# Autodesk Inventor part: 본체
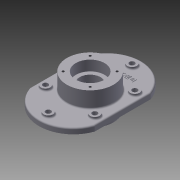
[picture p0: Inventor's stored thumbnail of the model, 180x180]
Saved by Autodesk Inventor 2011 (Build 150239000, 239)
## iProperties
Created: 2015-02
Part Number: 본체
Material: 알루미늄-6061
Document SubType Name: Modeling
Designer: Administrator
Mass: 1637.29 g
Surface Area: 924.766 cm^2
Volume: 604.167 cm^3
Density: 2.71 g/cm^3
Author: Administrator
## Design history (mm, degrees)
sketch "스케치1"
  geometry: C1 r 50 at (0, 0); 1 further point
  constraints: 1 centre point, 1 coincident
  dimensions: "d0" = 100 diameter of C1
extrude "돌출1" new body sketch "스케치1" distance "d1" = 23; taper "d2" = 0 deg
sketch "스케치2"
  geometry: L1 (-70, 0)-(-70, -60); L2 (70, -60)-(70, 60); L3 (-70, 60)-(-70, 0); A1 r 74 centre (0, -36) between (-70, -60) and (70, -60); A2 r 74 centre (0, 36) between (70, 60) and (-70, 60)
  constraints: 6 end point, 4 point on circle, 2 centre point
extrude "돌출2" join sketch "스케치2" distance "d3" = 12; taper "d4" = 0 deg
sketch "스케치3"
  geometry: C1 r 50 at (0, 0); 1 further point
  constraints: 1 centre point, 1 coincident
extrude "돌출3" join sketch "스케치3" distance "d5" = 35; taper "d6" = 0 deg
sketch "스케치6"
  geometry: C1 r 50 at (0, 0) reference; C2 r 31 at (0, 0)
  constraints: 1 centre point, 1 coincident
extrude "돌출5" cut sketch "스케치6" distance "d18" = 22; taper "d19" = 0 deg
sketch "스케치7"
  geometry: C1 r 50 at (0, 0) reference; C2 r 31 at (0, 0)
  constraints: 1 centre point, 1 coincident
extrude "돌출6" cut sketch "스케치7" distance "d20" = 22; taper "d21" = 0 deg
sketch "스케치8"
  geometry: C1 r 31 at (0, 0) reference; C2 r 22.5 at (0, 0)
  constraints: 1 centre point, 1 coincident
extrude "돌출7" cut sketch "스케치8" stored distance "d22" = 22; taper "d23" = 0 deg
sketch "스케치9"
  geometry: L1 (0, 0)-(28.991, 28.991); C1 r 50 at (0, 0) reference; 1 further point
  constraints: 2 coincident, 2 end point, 3 other
sketch "스케치10"
  geometry: L1 (0, 0)-(28.991, 28.991); C1 r 50 at (0, 0) reference; 1 further point
  constraints: 2 coincident, 2 end point, 3 other
hole "Hole2" sketch "스케치10" at (28.991, 28.991) diameter "d24" = 4.917; stored, may be unused: countersink angle "d28" = 90 deg, drill point angle "d30" = 118 deg; dims "d25" = 10, "d26" = 4, "d27" = 2, "d29" = 13
hole "Hole3" sketch "스케치9" diameter "d34" = 4.917; stored, may be unused: countersink angle "d38" = 90 deg, drill point angle "d40" = 118 deg; dims "d35" = 10, "d36" = 4, "d37" = 2, "d39" = 13
fillet "모깎기1" dims "d44" = 3
sketch "스케치11"
  geometry: A1 r 53 centre (0, 0) between (53, 0) and (53, 0) reference; 1 further point
  constraints: 1 vertical alignment, 1 other
  dimensions: "d45" = 65 distance of A1.centre point (0, 65)
feature "엠보싱1" sketch "스케치11" dims "d46" = 1, "d47" = 0
fillet "모깎기2" dims "d48" = 0.3
sketch "스케치12"
  geometry: L1 (67, 59.495)-(67, -59.495) reference; L2 (-53, 60)-(-53, -60); L3 (-70, 60)-(-70, -60) reference; L4 (53, 60)-(53, -60); L5 (70, -60)-(70, 60) reference; L6 (0, 90)-(0, 107); L7 (0, -90)-(0, -107); L8 (-53, 60)-(-53, 43); L9 (-53, -60)-(-53, -43); C1 r 10 at (0, -90); C2 r 10 at (-53, 43); C3 r 10 at (53, 43); C4 r 10 at (0, 90); C5 r 10 at (-53, -43); C6 r 10 at (53, -43); A1 r 71 centre (0, -36) between (-67, -59.495) and (67, -59.495) reference; A2 r 71 centre (0, 36) between (67, 59.495) and (-67, 59.495) reference; A3 r 61.817 centre (0, 28.183) between (53, 60) and (-53, 60); A4 r 61.817 centre (0, -28.183) between (-53, -60) and (53, -60); 4 further points
  constraints: 12 end point, 8 centre point, 8 point on circle, 4 coincident, 4 midpoint, 4 point on line, 2 horizontal alignment
  dimensions: "d49" = 17 distance between parallel lines of L2 L3; "d50" = 120 distance of L2.start L2.end; "d51" = 17 distance between parallel lines of L5 L4; "d52" = 17 distance of L6.start L6.end; "d53" = 120 distance of L4.start L4.end; "d54" = 17 distance of L7.start L7.end
extrude "돌출8" join sketch "스케치12" distance "d55" = 5; taper "d56" = 0 deg
sketch "스케치13"
  geometry: C1 r 10 at (0, 0) reference; C2 r 10 at (53, 47) reference; C3 r 10 at (106, 0) reference; C4 r 10 at (106, -86) reference; C5 r 10 at (0, -86) reference; C6 r 10 at (53, -133) reference; 1 further point
hole "Hole4" sketch "스케치13" at (53, 47), (0, 0), (0, -86), (53, -133), (106, -86), (106, 0) diameter "d57" = 11; stored, may be unused: countersink angle "d61" = 90 deg, drill point angle "d63" = 118 deg; dims "d58" = 6, "d59" = 4, "d60" = 2, "d62" = 8
fillet "모깎기3" dims "d64" = 3
node "솔리드1"
pattern_circular "원형 패턴1" dims angle "d32" = 360 deg
pattern_circular "원형 패턴2" dims angle "d42" = 360 deg
node "투영된 루프6"
node "투영된 루프7"
node "투영된 루프8"
node "투영된 루프9"
node "투영된 루프10"
